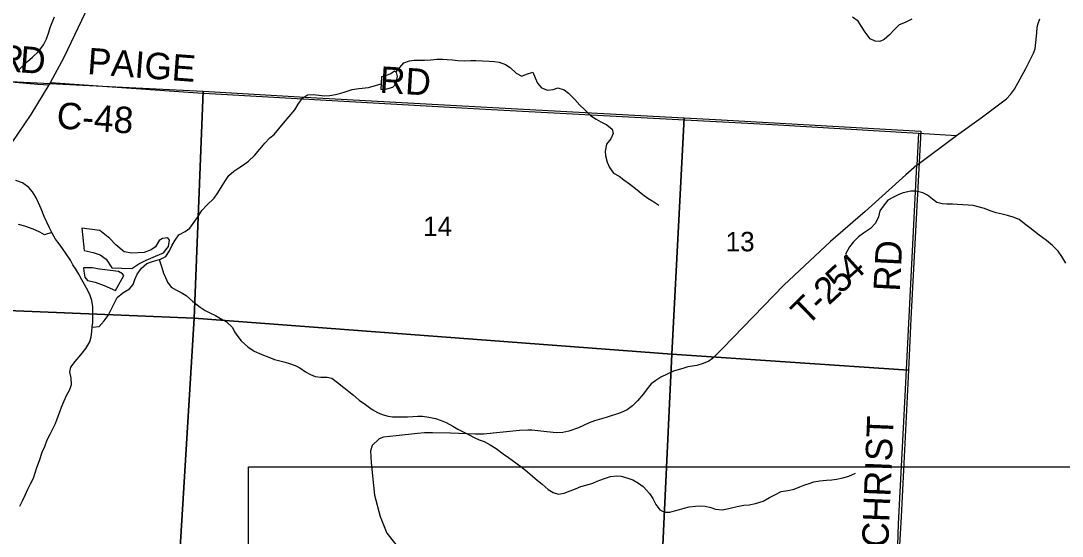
# Model space of a CAD drawing. Extents: x 1759416 to 2214760, y 252598 to 1116833.
# Drawn here: x 1981672 to 1993486, y 879628 to 885483 of the extents above; entities that cross this region are included whole.
import ezdxf

# ---------------------------------------------------------------- set-up
doc = ezdxf.new("R2010")
doc.units = 0
for name, color, linetype in [('GM_X_County_Road', 7, 'Continuous'), ('GM_X_County_Road_Text', 7, 'Continuous'), ('GM_X_Minor_Lake', 7, 'Continuous'), ('GM_X_Minor_River', 7, 'Continuous'), ('GM_X_Section', 7, 'Continuous'), ('GM_X_Section_Text', 7, 'Continuous'), ('GM_X_State_Route', 7, 'Continuous'), ('GM_X_Township_Road', 7, 'Continuous'), ('GM_X_Township_Road_Text', 7, 'Continuous'), ('SC_Scratch1', 7, 'Continuous')]:
    doc.layers.add(name, color=color, linetype=linetype)

msp = doc.modelspace()

# ---------------------------------------------------------------- linework, layer by layer
at = {"layer": 'GM_X_County_Road'}
for points in [[(1991595, 878673), (1991628, 879767), (1991704, 881224), (1991794, 883019), (1991839, 883842), (1992286, 884180), (1992568, 884380), (1992854, 884598), (1992899, 884646), (1992945, 884706), (1993075, 884940), (1993159, 885116), (1993179, 885164), (1993187, 885236), (1993197, 885345), (1993202, 885409), (1993212, 885451), (1993234, 885505)], [(1982009, 884782), (1983679, 884663), (1985468, 884563), (1986472, 884506), (1987011, 884475), (1988566, 884390), (1990200, 884304), (1991855, 884206), (1992286, 884180)]]:
    msp.add_lwpolyline(points, dxfattribs=at)
at = {"layer": 'GM_X_Minor_Lake'}
for points in [[(1985758, 884703), (1985824, 884708), (1985892, 884728), (1985928, 884768), (1985945, 884850), (1985935, 884894), (1985913, 884910), (1985869, 884880), (1985807, 884859), (1985763, 884847)], [(1985763, 884847), (1985758, 884703)], [(1982364, 883126), (1982391, 882873)], [(1982391, 882873), (1982493, 882851), (1982573, 882826), (1982639, 882776), (1982706, 882677), (1982930, 882668), (1983009, 882721), (1983095, 882763), (1983201, 882808), (1983292, 882846), (1983346, 882917), (1983359, 882989), (1983339, 883019), (1983281, 883008), (1983242, 882988), (1983200, 882916), (1983150, 882880), (1983073, 882851), (1982931, 882842), (1982845, 882860), (1982750, 882937), (1982680, 883008), (1982570, 883099), (1982364, 883126)], [(1982842, 882588), (1982824, 882610), (1982780, 882636), (1982566, 882662), (1982484, 882676), (1982384, 882675), (1982385, 882637), (1982397, 882571), (1982427, 882531), (1982515, 882512), (1982617, 882477), (1982746, 882420)], [(1982746, 882420), (1982842, 882588)]]:
    msp.add_lwpolyline(points, dxfattribs=at)
at = {"layer": 'GM_X_Minor_River'}
for points in [[(1981639, 884913), (1981696, 884971), (1981748, 885019), (1981804, 885069), (1981875, 885138), (1981929, 885208), (1981962, 885278), (1981988, 885354), (1982005, 885406), (1982027, 885464), (1982053, 885526)], [(1991782, 885502), (1991706, 885464), (1991636, 885436), (1991582, 885383), (1991529, 885325), (1991467, 885269), (1991416, 885246), (1991366, 885250), (1991309, 885278), (1991251, 885355), (1991211, 885419), (1991170, 885477), (1991108, 885522)], [(1985927, 884900), (1986016, 885006), (1986080, 885029), (1986134, 885037), (1986202, 885034), (1986252, 885034), (1986324, 885040), (1986390, 885047), (1986457, 885047), (1986509, 885043), (1986569, 885038), (1986631, 885032), (1986709, 885029), (1986777, 885033), (1986835, 885032), (1986909, 885028), (1986985, 885023), (1987043, 885019), (1987097, 885011), (1987169, 884986), (1987223, 884954), (1987292, 884887), (1987356, 884855), (1987408, 884875), (1987481, 884898), (1987508, 884836), (1987532, 884774), (1987580, 884723), (1987647, 884693), (1987710, 884702), (1987766, 884720), (1987836, 884699), (1987887, 884659), (1987957, 884587), (1988013, 884524), (1988066, 884476), (1988136, 884405), (1988198, 884365), (1988254, 884334), (1988320, 884302), (1988381, 884251), (1988391, 884201), (1988367, 884141), (1988316, 884083), (1988302, 884001), (1988305, 883947), (1988325, 883875), (1988351, 883817), (1988394, 883752), (1988460, 883716), (1988512, 883678), (1988578, 883629), (1988645, 883576), (1988727, 883508), (1988785, 883469), (1988841, 883433), (1988912, 883388)], [(1982483, 882004), (1982560, 882009), (1982616, 882075), (1982662, 882136), (1982699, 882210), (1982738, 882286), (1982766, 882338), (1982828, 882392), (1982903, 882437), (1982945, 882489), (1982967, 882545), (1982992, 882603), (1983040, 882671), (1983103, 882727), (1983155, 882746), (1983205, 882758), (1983255, 882774), (1983317, 882807), (1983360, 882871), (1983390, 882933), (1983421, 882989), (1983465, 883051), (1983535, 883088), (1983590, 883126), (1983628, 883180), (1983683, 883258), (1983727, 883328), (1983783, 883389), (1983864, 883467), (1983908, 883527), (1983955, 883607), (1983993, 883668), (1984032, 883726), (1984088, 883774), (1984145, 883814), (1984199, 883845), (1984253, 883889), (1984324, 883951), (1984384, 884024), (1984441, 884094), (1984495, 884152), (1984547, 884192), (1984598, 884257), (1984652, 884321), (1984715, 884395), (1984781, 884473), (1984820, 884536), (1984868, 884602), (1984925, 884642), (1984991, 884646), (1985051, 884637), (1985121, 884631), (1985177, 884634), (1985241, 884644), (1985301, 884660), (1985351, 884677), (1985431, 884701), (1985506, 884714), (1985618, 884726), (1985760, 884767)], [(1981662, 879971), (1981690, 880031), (1981721, 880093), (1981753, 880163), (1981782, 880223), (1981814, 880289), (1981855, 880409), (1981883, 880489), (1981914, 880583), (1981946, 880647), (1981971, 880721), (1982003, 880786), (1982038, 880854), (1982066, 880908), (1982086, 880960), (1982115, 881040), (1982133, 881092), (1982162, 881164), (1982190, 881226), (1982229, 881296), (1982247, 881352), (1982242, 881424), (1982226, 881496), (1982240, 881550), (1982289, 881614), (1982353, 881690), (1982410, 881759), (1982454, 881837), (1982469, 881891), (1982477, 881949), (1982483, 882005), (1982488, 882057), (1982490, 882107), (1982490, 882164), (1982487, 882234), (1982477, 882306), (1982460, 882362), (1982434, 882412), (1982396, 882489), (1982365, 882541), (1982331, 882605), (1982297, 882660), (1982262, 882710), (1982236, 882762), (1982188, 882837), (1982143, 882895), (1982105, 882951), (1982067, 883002), (1982028, 883070), (1981998, 883130), (1981965, 883197), (1981935, 883259), (1981903, 883345), (1981872, 883414), (1981842, 883480), (1981803, 883540), (1981761, 883590), (1981691, 883643), (1981617, 883668)], [(1993529, 882730), (1993481, 882804), (1993439, 882867), (1993378, 882931), (1993308, 882988), (1993226, 883046), (1993172, 883089), (1993121, 883129), (1993057, 883178), (1992997, 883226), (1992931, 883253), (1992867, 883271), (1992805, 883287), (1992739, 883302), (1992669, 883324), (1992606, 883351), (1992534, 883371), (1992476, 883384), (1992418, 883390), (1992358, 883392), (1992300, 883397), (1992242, 883399), (1992177, 883398), (1992125, 883404), (1992066, 883420), (1992014, 883457), (1991958, 883501), (1991904, 883528), (1991828, 883546), (1991768, 883546), (1991682, 883527), (1991632, 883511), (1991573, 883480), (1991509, 883446), (1991467, 883394), (1991418, 883324), (1991402, 883254), (1991369, 883184), (1991311, 883125), (1991231, 883071), (1991176, 883029), (1991120, 882972), (1991073, 882914), (1991027, 882830)], [(1982024, 883078), (1981942, 883052), (1981888, 883081), (1981830, 883107), (1981772, 883132), (1981716, 883148), (1981644, 883169)], [(1983243, 882770), (1983270, 882679), (1983290, 882617), (1983314, 882565), (1983336, 882515), (1983379, 882458), (1983437, 882424), (1983491, 882396), (1983549, 882363), (1983624, 882294), (1983706, 882230), (1983764, 882193), (1983816, 882165), (1983882, 882135), (1983939, 882102), (1984007, 882062), (1984073, 881999), (1984095, 881949), (1984132, 881897), (1984172, 881846), (1984246, 881780), (1984319, 881731), (1984405, 881691), (1984485, 881662), (1984551, 881634), (1984655, 881607), (1984707, 881592), (1984783, 881566), (1984837, 881542), (1984903, 881497), (1984958, 881465), (1985012, 881444), (1985074, 881434), (1985148, 881435), (1985202, 881425), (1985266, 881375), (1985338, 881316), (1985392, 881270), (1985445, 881231), (1985509, 881173), (1985583, 881124), (1985659, 881068), (1985720, 881035), (1985772, 881011), (1985840, 880990), (1985890, 880984), (1986010, 880983), (1986060, 880985), (1986118, 880986), (1986177, 880990), (1986229, 880990), (1986301, 880979), (1986375, 880965), (1986442, 880942), (1986496, 880920), (1986572, 880877), (1986628, 880845), (1986698, 880808), (1986750, 880784), (1986816, 880750), (1986871, 880723), (1986927, 880703), (1986997, 880666), (1987063, 880624), (1987145, 880563), (1987205, 880521), (1987286, 880460), (1987358, 880410), (1987422, 880359), (1987477, 880309), (1987529, 880264), (1987587, 880218), (1987655, 880157), (1987710, 880123), (1987770, 880106), (1987835, 880118), (1987903, 880142), (1987963, 880165), (1988025, 880191), (1988097, 880211), (1988162, 880232), (1988212, 880254), (1988294, 880285), (1988362, 880305), (1988432, 880313), (1988482, 880310), (1988560, 880288), (1988614, 880267), (1988680, 880231), (1988734, 880194), (1988805, 880114), (1988841, 880058), (1988875, 879989), (1988922, 879927), (1988976, 879902), (1989036, 879900), (1989088, 879916), (1989145, 879931), (1989197, 879947), (1989255, 879961), (1989327, 879970)], [(1989327, 879970), (1989385, 879974), (1989435, 879970), (1989501, 879953), (1989553, 879935), (1989629, 879928), (1989703, 879944), (1989765, 879959), (1989817, 879969), (1989876, 879979), (1989936, 879986), (1990008, 880000), (1990094, 880025), (1990166, 880067), (1990225, 880097), (1990299, 880134), (1990373, 880148), (1990447, 880163), (1990508, 880187), (1990566, 880211), (1990616, 880226), (1990670, 880244), (1990736, 880258), (1990812, 880263), (1990872, 880269), (1990924, 880277), (1990997, 880290), (1991065, 880310), (1991143, 880343)]]:
    msp.add_lwpolyline(points, dxfattribs=at)
at = {"layer": 'GM_X_Section'}
for points in [[(1978370, 884986), (1980578, 884841), (1982749, 884734), (1983740, 884682), (1983640, 882103), (1978208, 882329), (1978281, 883552)], [(1983740, 884682), (1984961, 884610), (1987234, 884487), (1989198, 884382), (1989058, 881695), (1983640, 882103)], [(1989554, 884361), (1991881, 884230), (1991770, 882097), (1991741, 881513), (1989058, 881695), (1989198, 884382)], [(1983640, 882103), (1983297, 876521), (1977894, 876803), (1977973, 878196), (1978208, 882329)], [(1989058, 881695), (1988799, 876231), (1983297, 876521), (1983640, 882103)], [(1989058, 881695), (1991741, 881513), (1991658, 879847), (1991538, 877797), (1991436, 876063), (1988799, 876231)]]:
    msp.add_lwpolyline(points, close=True, dxfattribs=at)
at = {"layer": 'GM_X_State_Route'}
msp.add_lwpolyline([(1981096, 883453), (1981250, 883656), (1981572, 884101), (1981789, 884419), (1981995, 884755), (1982009, 884782), (1982163, 885071), (1982443, 885656), (1982796, 886554), (1983044, 887232), (1983277, 887878), (1983358, 888104), (1983440, 888403), (1983564, 888762), (1983595, 888877), (1983687, 889125), (1983733, 889226), (1983782, 889319), (1984056, 889807), (1984189, 890041)], dxfattribs=at)
at = {"layer": 'GM_X_Township_Road'}
for points in [[(1979291, 885921), (1979325, 885819), (1979378, 885634), (1979393, 885538), (1979408, 885308), (1979410, 884961), (1979418, 884931), (1979446, 884901), (1979508, 884885), (1980408, 884868), (1981391, 884806), (1981866, 884762), (1981995, 884755)], [(1991855, 884206), (1991839, 883842), (1991713, 883734), (1991252, 883318), (1990859, 882974), (1990328, 882481), (1989635, 881765), (1989519, 881647), (1989477, 881615), (1989415, 881589), (1989341, 881569), (1989265, 881556)], [(1989265, 881556), (1989241, 881551), (1989195, 881538), (1989075, 881501), (1988931, 881435), (1988876, 881397), (1988822, 881357), (1988778, 881303), (1988736, 881245), (1988668, 881167), (1988612, 881109), (1988552, 881063), (1988474, 881029), (1988314, 880975), (1988181, 880938), (1988119, 880914), (1987999, 880858), (1987891, 880822), (1987821, 880806), (1987749, 880804), (1987639, 880812), (1987471, 880834), (1987425, 880834), (1987329, 880830), (1986921, 880787), (1986831, 880789), (1986546, 880799), (1986344, 880803), (1986252, 880801), (1986174, 880793), (1985930, 880770), (1985786, 880752), (1985736, 880736), (1985656, 880659), (1985640, 880597), (1985648, 880460), (1985685, 880093), (1985747, 879853), (1985826, 879663), (1986086, 879332)]]:
    msp.add_lwpolyline(points, dxfattribs=at)
at = {"layer": 'SC_Scratch1'}
msp.add_lwpolyline([(1984253, 880416), (2020157, 880416), (2020157, 844512), (1984253, 844512)], close=True, dxfattribs=at)

# ---------------------------------------------------------------- texts
at = {"layer": 'GM_X_County_Road_Text'}
for s, rotation, p in [('PAIGE', 355.7986, (1982421, 884878)), ('RD', 356.5466, (1985737, 884667)), ('C-48', 355.8896, (1982071, 884262)), ('RD', 87.0388, (1991644, 882403)), ('GILCHRIST', 87.6312, (1991486, 878849))]:
    msp.add_text(s, height=300, rotation=rotation, dxfattribs=at).set_placement(p)
at = {"layer": 'GM_X_Section_Text'}
for s, p in [('14', (1986236, 883037)), ('13', (1989668, 882864))]:
    msp.add_text(s, height=221, rotation=0, dxfattribs=at).set_placement(p)
at = {"layer": 'GM_X_Township_Road_Text'}
for s, rotation, p in [('R', 354.7197, (1981402, 884921)), ('D', 355.6424, (1981653, 884898)), ('4', 42.0769, (1991109, 882495)), ('5', 42.7547, (1990974, 882370)), ('2', 42.8026, (1990839, 882245)), ('T', 44.7667, (1990592, 882004)), ('-', 43.1065, (1990749, 882161))]:
    msp.add_text(s, height=300, rotation=rotation, dxfattribs=at).set_placement(p)

doc.saveas('drawing.dxf')
